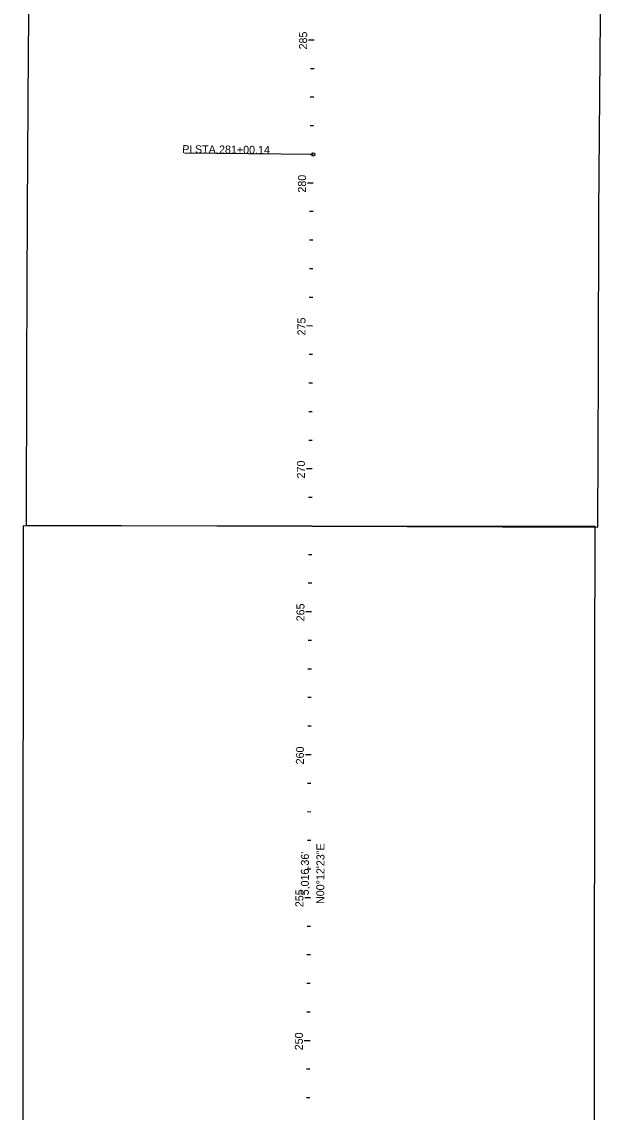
# Model space of a CAD drawing. Extents: x 1807668 to 1809726, y 297763 to 325145.
# Drawn here: x 1807668 to 1809726, y 305319 to 309133 of the extents above; entities that cross this region are included whole.
import ezdxf

# ---------------------------------------------------------------- set-up
doc = ezdxf.new("R2010")
doc.units = 0
for name, color, linetype in [('GE_P_Alignment_500_Bearings', 7, 'Continuous'), ('GE_P_Alignment_500_Cardinal_Points', 7, 'Continuous'), ('GE_P_Alignment_500_Distances', 7, 'Continuous'), ('GE_P_Alignment_500_Stations', 7, 'Continuous'), ('SH_Named_Boundary', 7, 'Continuous')]:
    doc.layers.add(name, color=color, linetype=linetype)

msp = doc.modelspace()

# ---------------------------------------------------------------- linework, layer by layer
at = {"layer": 'GE_P_Alignment_500_Cardinal_Points'}
msp.add_line((1808687.5, 308669.3), (1808237.5, 308673.4), dxfattribs=at)
msp.add_circle((1808687.5, 308669.3), 6, dxfattribs=at)
at = {"layer": 'GE_P_Alignment_500_Stations'}
for p, q in [((1808691.1, 309069.2), (1808671.1, 309069.4)), ((1808690.2, 308969.2), (1808678.2, 308969.3)), ((1808689.3, 308869.2), (1808677.3, 308869.3)), ((1808688.4, 308769.2), (1808676.4, 308769.3)), ((1808687.5, 308669.2), (1808675.5, 308669.2)), ((1808687.1, 308569.2), (1808667.1, 308569.3)), ((1808686.8, 308469.2), (1808674.8, 308469.2)), ((1808686.4, 308369.2), (1808674.4, 308369.2)), ((1808686.1, 308269.2), (1808674.1, 308269.2)), ((1808685.7, 308169.2), (1808673.7, 308169.2)), ((1808685.3, 308069.2), (1808665.3, 308069.3)), ((1808685, 307969.2), (1808673, 307969.2)), ((1808684.6, 307869.2), (1808672.6, 307869.2)), ((1808684.3, 307769.2), (1808672.3, 307769.2)), ((1808683.9, 307669.2), (1808671.9, 307669.2)), ((1808683.5, 307569.2), (1808663.5, 307569.3)), ((1808683.2, 307469.2), (1808671.2, 307469.2)), ((1808682.8, 307369.2), (1808670.8, 307369.2)), ((1808682.5, 307269.2), (1808670.5, 307269.2)), ((1808682.1, 307169.2), (1808670.1, 307169.2)), ((1808681.7, 307069.2), (1808661.7, 307069.3)), ((1808681.4, 306969.2), (1808669.4, 306969.2)), ((1808681, 306869.2), (1808669, 306869.3)), ((1808680.7, 306769.2), (1808668.7, 306769.3)), ((1808680.3, 306669.2), (1808668.3, 306669.3)), ((1808679.9, 306569.2), (1808659.9, 306569.3)), ((1808679.6, 306469.2), (1808667.6, 306469.3)), ((1808679.2, 306369.2), (1808667.2, 306369.3)), ((1808678.9, 306269.2), (1808666.9, 306269.3)), ((1808678.5, 306169.2), (1808666.5, 306169.3)), ((1808678.1, 306069.2), (1808658.1, 306069.3)), ((1808677.8, 305969.2), (1808665.8, 305969.3)), ((1808677.4, 305869.2), (1808665.4, 305869.3)), ((1808677.1, 305769.2), (1808665.1, 305769.3)), ((1808676.7, 305669.2), (1808664.7, 305669.3)), ((1808676.3, 305569.2), (1808656.3, 305569.3)), ((1808676, 305469.2), (1808664, 305469.3)), ((1808675.6, 305369.2), (1808663.6, 305369.3))]:
    msp.add_line(p, q, dxfattribs=at)
at = {"layer": 'SH_Named_Boundary'}
for points in [[(1807682.8, 307372.8), (1809682.8, 307365.6), (1809684.8, 307915.6), (1809686.8, 308465.6), (1809690.6, 309010.2), (1809695.6, 309560.1), (1809700.5, 310110.1), (1809705.5, 310660.1), (1809710.5, 311210.1), (1809715.6, 311759.4), (1809720.9, 312309.4), (1809726.2, 312859.4), (1807726.3, 312878.7), (1807721, 312328.7), (1807715.7, 311778.7), (1807710.5, 311228.1), (1807705.6, 310678.1), (1807700.6, 310128.2), (1807695.7, 309578.2), (1807690.7, 309028.2), (1807686.8, 308472.8), (1807684.8, 307922.8)], [(1807668.1, 302370.2), (1809668.1, 302368.2), (1809668.6, 302868.2), (1809669.2, 303368.2), (1809669.7, 303868.2), (1809670.2, 304368.2), (1809670.7, 304868.2), (1809671.2, 305368.2), (1809671.7, 305868.2), (1809672.2, 306368.2), (1809672.7, 306868.2), (1809673.2, 307368.2), (1807673.2, 307370.3), (1807672.7, 306870.3), (1807672.2, 306370.3), (1807671.7, 305870.3), (1807671.2, 305370.3), (1807670.7, 304870.2), (1807670.2, 304370.2), (1807669.7, 303870.2), (1807669.2, 303370.2), (1807668.6, 302870.2)]]:
    msp.add_lwpolyline(points, close=True, dxfattribs=at)

# ---------------------------------------------------------------- texts
at = {"layer": 'GE_P_Alignment_500_Bearings'}
msp.add_text('N00°12\'23"E', height=28, rotation=89.7937, dxfattribs=at).set_placement((1808726.1, 306047.4))
at = {"layer": 'GE_P_Alignment_500_Cardinal_Points'}
for s, p in [('PI', (1808229.3, 308673.9)), (' STA. ', (1808263.2, 308673.6)), ('281+00.14', (1808357.8, 308672.7))]:
    msp.add_text(s, height=28, rotation=359.4832, dxfattribs=at).set_placement(p)
at = {"layer": 'GE_P_Alignment_500_Distances'}
msp.add_text("5,016.36'", height=28, rotation=89.7937, dxfattribs=at).set_placement((1808671.9, 306077.7))
at = {"layer": 'GE_P_Alignment_500_Stations'}
for s, rotation, p in [('285', 89.4832, (1808665.8, 309036.4)), ('280', 89.7937, (1808662, 308535.8)), ('275', 89.7937, (1808660.2, 308036.2)), ('270', 89.7937, (1808658.4, 307535.8)), ('265', 89.7937, (1808656.6, 307036.2)), ('260', 89.7937, (1808654.8, 306535.8)), ('255', 89.7937, (1808653, 306036.3)), ('250', 89.7937, (1808651.2, 305535.8))]:
    msp.add_text(s, height=28, rotation=rotation, dxfattribs=at).set_placement(p)

doc.saveas('drawing.dxf')
